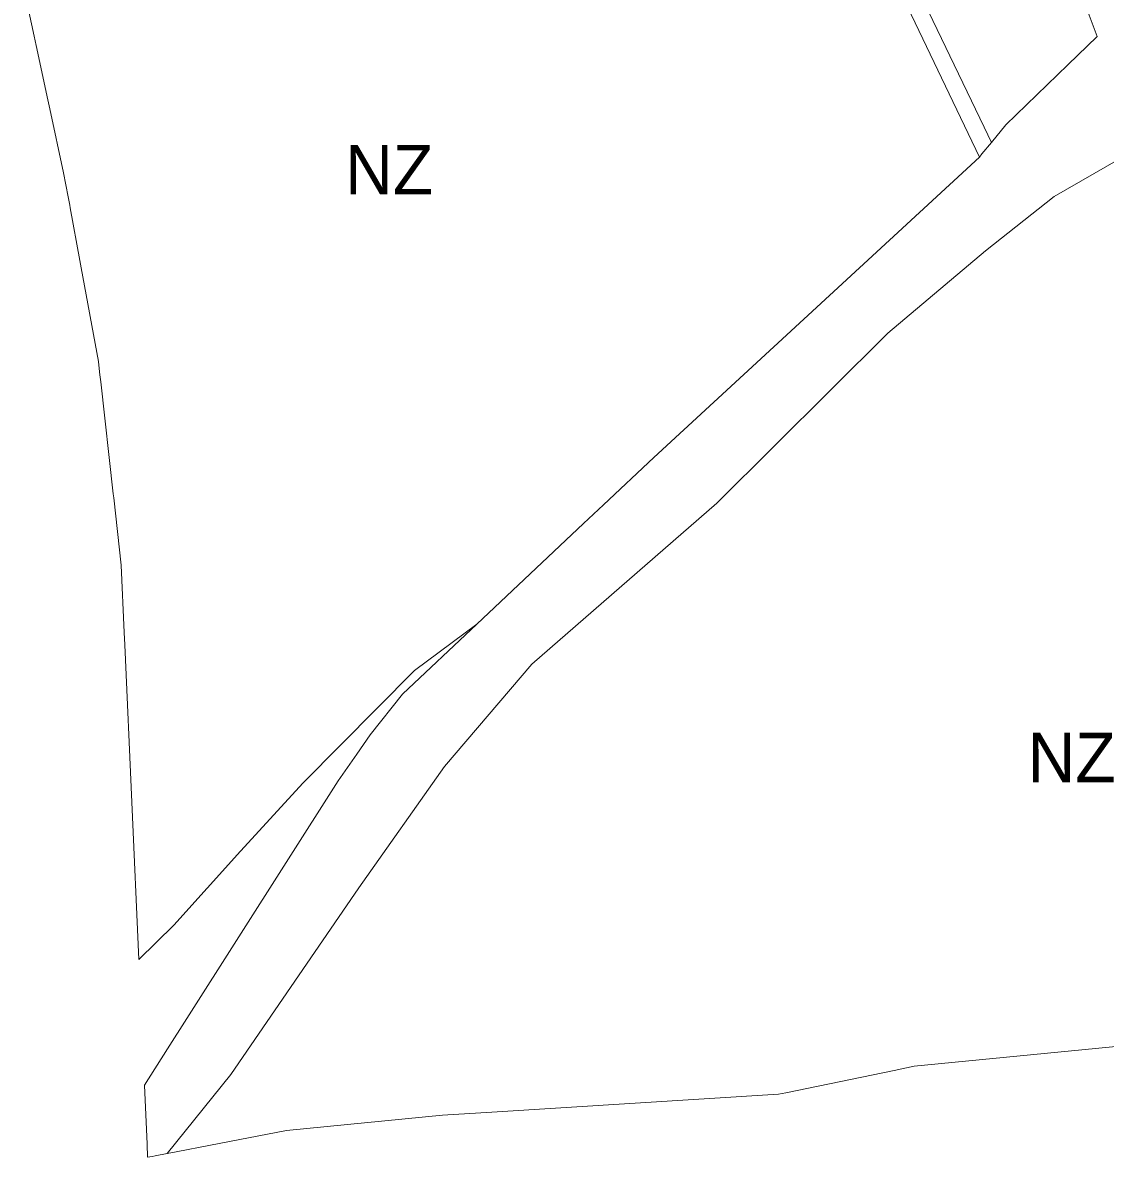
# Model space of a CAD drawing. Extents: x -650451 to -642268, y -1075216 to -1066610.
# Drawn here: x -645088.2 to -644825.3, y -1073664.6 to -1073388.9 of the extents above; entities that cross this region are included whole.
import ezdxf

# ---------------------------------------------------------------- set-up
doc = ezdxf.new("R2010")
doc.units = 0
doc.header["$LTSCALE"] = 4.8
for name, color, linetype, lineweight in [('24', 7, 'Continuous', 13), ('3', 7, 'Continuous', 13), ('46', 7, 'Continuous', 13), ('48', 7, 'Continuous', 13)]:
    doc.layers.add(name, color=color, linetype=linetype, lineweight=lineweight)
doc.layers.add('62', color=7, linetype='Continuous')

msp = doc.modelspace()

# ---------------------------------------------------------------- linework, layer by layer
at = {"layer": '24'}
for points in [[(-644852.94, -1073418.04), (-644849.42, -1073413.72), (-644834.38, -1073399.18), (-644827.25, -1073392.29), (-644830.43, -1073383.91), (-644838.85, -1073365.29), (-644855.23, -1073329.01), (-644866.71, -1073303.59)], [(-644855.81, -1073421.57), (-644855.22, -1073420.84), (-644852.94, -1073418.04)], [(-644754.41, -1073629.99), (-644785.78, -1073524.66), (-644809.35, -1073445.51), (-644811.95, -1073440), (-644819.19, -1073422.9), (-644821.51, -1073421.83), (-644837.65, -1073431.13), (-644854.34, -1073444.4), (-644878.09, -1073464.33), (-644919.6, -1073505.63), (-644964.57, -1073544.75), (-644985.78, -1073569.64), (-645006.55, -1073599.09), (-645037.66, -1073644.42), (-645053.13, -1073663.63)], [(-644977.924, -1073535.072), (-644952.02, -1073510.63), (-644947.18, -1073506.06), (-644934.91, -1073494.57), (-644855.81, -1073421.57)], [(-645058.65, -1073647), (-645053.02, -1073638.21), (-645048.32, -1073630.82), (-645011.61, -1073573.07), (-645007.1, -1073566.62), (-645003.83, -1073561.94), (-644995.96, -1073552.09), (-644977.924, -1073535.072)], [(-645053.13, -1073663.63), (-645056.06, -1073664.2), (-645056.8, -1073664.34), (-645057.87, -1073664.55), (-645058.01, -1073661.37), (-645058.65, -1073647)]]:
    msp.add_lwpolyline(points, dxfattribs=at)
at = {"layer": '3'}
for points in [[(-644852.94, -1073418.04), (-644854.72, -1073414.33), (-644872.35, -1073377.53), (-644888.29, -1073344), (-644903.66, -1073311.34), (-644903.92, -1073299.4), (-644911.461, -1073299.98), (-644914.85, -1073289.05)], [(-644866.71, -1073303.59), (-644855.23, -1073329.01), (-644838.85, -1073365.29), (-644830.43, -1073383.91), (-644827.25, -1073392.29), (-644834.38, -1073399.18), (-644849.42, -1073413.72), (-644852.94, -1073418.04)]]:
    msp.add_lwpolyline(points, dxfattribs=at)
at = {"layer": '46'}
for points in [[(-644911.461, -1073299.98), (-644907.47, -1073312.85), (-644891.94, -1073345.72), (-644876.05, -1073379.3), (-644855.81, -1073421.57)], [(-645060.01, -1073616.531), (-645063.42, -1073540.09), (-645063.55, -1073537.04), (-645064.28, -1073520.73), (-645066.11, -1073504.38), (-645066.22, -1073503.38), (-645069.27, -1073476.16), (-645069.45, -1073474.51), (-645069.63, -1073472.94), (-645069.82, -1073471.22), (-645074, -1073448.52), (-645074.34, -1073446.7), (-645076.69, -1073433.94), (-645076.81, -1073433.27), (-645077.19, -1073431.24), (-645078.27, -1073425.38), (-645081.62, -1073409.9), (-645082.11, -1073407.66), (-645084.96, -1073394.48), (-645085.46, -1073392.18), (-645088.22, -1073379.41)], [(-645053.13, -1073663.63), (-645037.66, -1073644.42), (-645006.55, -1073599.09), (-644985.78, -1073569.64), (-644964.57, -1073544.75), (-644919.6, -1073505.63), (-644878.09, -1073464.33), (-644854.34, -1073444.4), (-644837.65, -1073431.13), (-644821.51, -1073421.83), (-644819.19, -1073422.9), (-644811.95, -1073440), (-644809.35, -1073445.51), (-644785.78, -1073524.66), (-644754.41, -1073629.99)], [(-644855.81, -1073421.57), (-644934.91, -1073494.57), (-644947.18, -1073506.06), (-644952.02, -1073510.63), (-644977.924, -1073535.072), (-644993.044, -1073546.324), (-645020.11, -1073573.585)], [(-645020.11, -1073573.585), (-645035.303, -1073590.199), (-645051.513, -1073608.124), (-645060.01, -1073616.531)], [(-644754.41, -1073629.99), (-644792.87, -1073634.74), (-644817.66, -1073637.16), (-644871.71, -1073642.42), (-644876.58, -1073643.43), (-644902.83, -1073648.86), (-644904.61, -1073649.23), (-644974.31, -1073653.58), (-644986.25, -1073654.32), (-645024.12, -1073658.01), (-645042.62, -1073661.59), (-645050.98, -1073663.21), (-645053.13, -1073663.63)]]:
    msp.add_lwpolyline(points, dxfattribs=at)
at = {"layer": '48'}
for points in [[(-644911.461, -1073299.98), (-644903.92, -1073299.4), (-644903.66, -1073311.34), (-644888.29, -1073344), (-644872.35, -1073377.53), (-644854.72, -1073414.33), (-644852.94, -1073418.04)], [(-644855.81, -1073421.57), (-644876.05, -1073379.3), (-644891.94, -1073345.72), (-644907.47, -1073312.85), (-644911.461, -1073299.98)], [(-644852.94, -1073418.04), (-644855.22, -1073420.84), (-644855.81, -1073421.57)]]:
    msp.add_lwpolyline(points, dxfattribs=at)

# ---------------------------------------------------------------- texts
at = {"layer": '62'}
for p in [(-645009.913, -1073430.649), (-644844.134, -1073573.442)]:
    msp.add_text('NZ', height=12, dxfattribs=at).set_placement(p)

doc.saveas('drawing.dxf')
